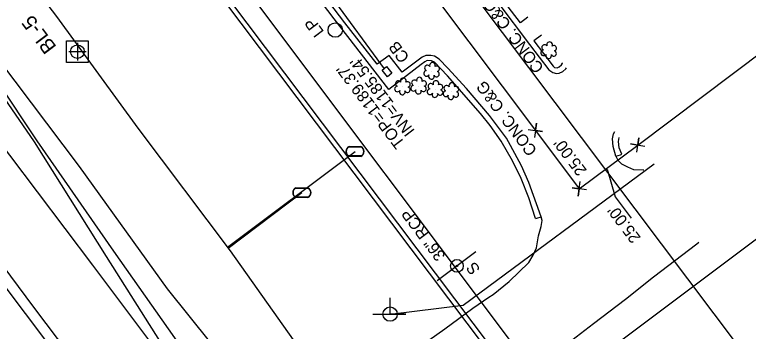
# Model space of a CAD drawing. Extents: x 1262092 to 1264624, y 774970 to 778314.
# Drawn here: x 1263792.5 to 1264043.6, y 776024.1 to 776132.5 of the extents above; entities that cross this region are included whole.
import ezdxf

# ---------------------------------------------------------------- set-up
doc = ezdxf.new("R2010")
doc.units = 0
for name, color, linetype in [('COGO Default Parcel', 7, 'Continuous'), ('Cogo Default Point CELL', 7, 'Continuous'), ('CTL Secondary Horizontal and Vertical CELL', 7, 'Continuous'), ('Exist Horizontal Alignment Station Label', 7, 'Continuous'), ('Exist Horizontal Alignment Tick Large', 7, 'Continuous'), ('Exist Property Corner CELL', 7, 'Continuous'), ('Exist Property Line', 7, 'Continuous'), ('Exist Property Line Leader', 7, 'Continuous'), ('Exist Property Line Text', 7, 'Continuous'), ('Exist Right of Way Easement Line', 7, 'Continuous'), ('Exist Right of Way Line', 7, 'Continuous'), ('Exist Roads Curbs', 7, 'Continuous'), ('Exist Roads EOP', 7, 'Continuous'), ('Exist Roads EOP Other', 7, 'Continuous'), ('Exist Roads EOT', 7, 'Continuous'), ('Exist Structure Minor Catch Basin Text', 7, 'Continuous'), ('Exist Structure Minor Drop Inlet', 7, 'Continuous'), ('Exist Structure Minor Drop Inlet Top Elevation', 7, 'Continuous'), ('Exist Structure Minor Pipes HDPE 15 Inch', 7, 'Continuous'), ('Exist Structure Minor Pipes HDPE 15 Inch Invert', 7, 'Continuous'), ('Exist Structure Minor Pipes RCP 36 Inch', 7, 'Continuous'), ('Exist Structure Minor Pipes RCP 36 Inch Text', 7, 'Continuous'), ('Exist Utilities Gas UG Line SUE LOS B', 7, 'Continuous'), ('Exist Utilities Other Pole Text', 7, 'Continuous'), ('Exist Utilities Power Joint Use Telephone CELL', 7, 'Continuous'), ('Exist Utilities Power UG Cable SUE LOS B', 7, 'Continuous'), ('Exist Utilities Water Meter CELL', 7, 'Continuous'), ('Exist Utilities Water UG Line SUE LOS B', 7, 'Continuous'), ('Prop Conc 4in Sidewalk', 7, 'Continuous'), ('Prop Paved Shoulder', 7, 'Continuous'), ('Sheet Plot Border Outside CELL', 7, 'Continuous')]:
    doc.layers.add(name, color=color, linetype=linetype)

# ---------------------------------------------------------------- blocks, each defined once
blk = doc.blocks.new('CTL SECONDARY HORIZONTAL AND VERTICAL')
at = {"layer": 'CTL Secondary Horizontal and Vertical CELL'}
blk.add_line((0, 0), (0, 0), dxfattribs=at)
blk.add_lwpolyline([(-0.1043, 0.0004), (0.0005, 0.1052), (0.1055, 0.0002), (0.0007, -0.1047)], close=True, dxfattribs=at)
blk = doc.blocks.new('EXIST UTILITIES WATER METER')
at = {"layer": 'Exist Utilities Water Meter CELL'}
blk.add_line((0, 0), (0, 0), dxfattribs=at)
for points in [[(-0.0408, 0.034), (0.0408, 0.034)], [(-0.0408, 0.0312), (0.0408, 0.0312)], [(0.0408, -0.0312), (-0.0413, -0.0312)], [(0.0408, -0.034), (-0.0413, -0.034)]]:
    blk.add_lwpolyline(points, dxfattribs=at)
for centre, radius, start, end in [((-0.0261, -0.0001), 0.0371, 113.178, 245.9794), ((-0.0259, -0.0001), 0.0347, 115.3009, 243.7824), ((0.0259, 0), 0.0371, 293.6483, 66.3084), ((0.0261, 0), 0.0345, 295.1272, 64.8728)]:
    blk.add_arc(centre, radius, start, end, dxfattribs=at)

msp = doc.modelspace()

# ---------------------------------------------------------------- linework, layer by layer
at = {"layer": 'COGO Default Parcel'}
msp.add_line((1263602.12, 776600.93), (1264624.2, 775243.33), dxfattribs=at)
at = {"layer": 'Cogo Default Point CELL'}
for points in [[(1263813.99, 776122.81), (1263813.99, 776119.81)], [(1263810.99, 776119.81), (1263813.99, 776119.81)], [(1263813.99, 776119.81), (1263816.99, 776119.81)], [(1263813.99, 776119.81), (1263813.99, 776116.81)]]:
    msp.add_lwpolyline(points, dxfattribs=at)
msp.add_circle((1263813.99, 776119.81), 2.34, dxfattribs=at)
at = {"layer": 'Exist Horizontal Alignment Station Label'}
msp.add_line((1263950.33, 776051.32), (1263937.11, 776041.42), dxfattribs=at)
for radius in [2.18, 0.24]:
    msp.add_circle((1263943.85, 776046.53), radius, dxfattribs=at)
at = {"layer": 'Exist Horizontal Alignment Tick Large'}
for p, q in [((1263975.34, 776120.1), (1263975.34, 776120.1)), ((1263935.25, 776113.07), (1263935.25, 776113.07)), ((1263925.29, 776107.72), (1263925.29, 776107.72)), ((1263930.8, 776108.01), (1263930.8, 776108.01)), ((1263936.44, 776106.81), (1263936.44, 776106.81)), ((1263941.87, 776106.12), (1263941.87, 776106.12))]:
    msp.add_line(p, q, dxfattribs=at)
for centre, radius, start, end in [((1263975.57, 776122.14), 0.99, 334.8391, 200.4717), ((1263973.54, 776119.39), 0.955, 95.1099, 327.9534), ((1263973.85, 776121.22), 0.968, 35.8908, 245.4216), ((1263977.01, 776120.97), 0.929, 284.4567, 126.0861), ((1263975.21, 776118.41), 0.984, 151.2797, 21.387), ((1263976.97, 776119.17), 0.937, 204.9913, 73.4601), ((1263933.77, 776114.2), 0.968, 35.8908, 245.4216), ((1263935.48, 776115.11), 0.99, 334.8391, 200.4717), ((1263933.45, 776112.37), 0.955, 95.1099, 327.9534), ((1263936.89, 776112.14), 0.937, 204.9913, 73.4601), ((1263936.93, 776113.94), 0.929, 284.4567, 126.0861), ((1263925.52, 776109.76), 0.99, 334.8391, 200.4717), ((1263931.03, 776110.05), 0.99, 334.8391, 200.4717), ((1263935.12, 776111.39), 0.984, 151.2797, 21.387), ((1263923.49, 776107.02), 0.955, 95.1099, 327.9534), ((1263923.8, 776108.85), 0.968, 35.8908, 245.4216), ((1263926.92, 776106.79), 0.937, 204.9913, 73.4601), ((1263926.96, 776108.59), 0.929, 284.4567, 126.0861), ((1263929, 776107.3), 0.955, 95.1099, 327.9534), ((1263929.32, 776109.13), 0.968, 35.8908, 245.4216), ((1263932.44, 776107.08), 0.937, 204.9913, 73.4601), ((1263932.47, 776108.88), 0.929, 284.4567, 126.0861), ((1263934.95, 776107.94), 0.968, 35.8908, 245.4216), ((1263936.66, 776108.85), 0.99, 334.8391, 200.4717), ((1263938.11, 776107.68), 0.929, 284.4567, 126.0861), ((1263940.39, 776107.25), 0.968, 35.8908, 245.4216), ((1263942.1, 776108.16), 0.99, 334.8391, 200.4717), ((1263943.54, 776106.99), 0.929, 284.4567, 126.0861), ((1263925.16, 776106.04), 0.984, 151.2797, 21.387), ((1263930.67, 776106.32), 0.984, 151.2797, 21.387), ((1263934.63, 776106.1), 0.955, 95.1099, 327.9534), ((1263936.31, 776105.13), 0.984, 151.2797, 21.387), ((1263938.07, 776105.88), 0.937, 204.9913, 73.4601), ((1263940.07, 776105.42), 0.955, 95.1099, 327.9534), ((1263943.51, 776105.19), 0.937, 204.9913, 73.4601), ((1263941.74, 776104.44), 0.984, 151.2797, 21.387)]:
    msp.add_arc(centre, radius, start, end, dxfattribs=at)
at = {"layer": 'Exist Property Corner CELL'}
for p, q in [((1263970.72, 776092.86), (1263970.72, 776092.86)), ((1264005.72, 776087.87), (1264005.72, 776087.87)), ((1263985.72, 776072.87), (1263985.72, 776072.87))]:
    msp.add_line(p, q, dxfattribs=at)
for points in [[(1263968.24, 776093.21), (1263973.19, 776092.51), (1263970.72, 776092.86), (1263971.07, 776095.34), (1263970.36, 776090.39)], [(1264005.37, 776085.4), (1264006.07, 776090.35), (1264005.72, 776087.87), (1264003.24, 776088.22), (1264008.19, 776087.52)], [(1263988.2, 776072.51), (1263983.25, 776073.22), (1263985.72, 776072.87), (1263985.37, 776070.39), (1263986.08, 776075.34)]]:
    msp.add_lwpolyline(points, dxfattribs=at)
at = {"layer": 'Exist Property Line'}
for p, q in [((1263879.77, 776214.05), (1263970.72, 776092.86)), ((1264005.72, 776087.87), (1264124.93, 776177.33)), ((1263970.72, 776092.86), (1263985.72, 776072.87)), ((1263985.72, 776072.87), (1264005.72, 776087.87))]:
    msp.add_line(p, q, dxfattribs=at)
at = {"layer": 'Exist Property Line Leader'}
msp.add_lwpolyline([(1263995.3, 776079.59), (1263997.97, 776070.12), (1264003.43, 776062.87)], dxfattribs=at)
at = {"layer": 'Exist Right of Way Easement Line'}
for q in [(1263824.78, 776204.04), (1264214.93, 776182.35)]:
    msp.add_line((1263975.74, 776002.86), q, dxfattribs=at)
at = {"layer": 'Exist Right of Way Line'}
msp.add_line((1263590.4, 776500.74), (1264585.76, 775179.25), dxfattribs=at)
at = {"layer": 'Exist Roads Curbs'}
for points in [[(1263970.77, 776062.71), (1263968.43, 776069.85), (1263965.8, 776076.37), (1263962.89, 776082.43), (1263959.02, 776089.14), (1263955.18, 776094.49), (1263951.97, 776098.62), (1263940.6, 776111.57), (1263936.2, 776116.19), (1263935.12, 776116.72), (1263933.7, 776116.74), (1263932.93, 776116.36), (1263931.67, 776115.39), (1263920.52, 776106.91), (1263901.9, 776131.06), (1263887.03, 776150.59)], [(1263968.15, 776131.58), (1263965.61, 776129.67), (1263959.42, 776137.8), (1263958.9, 776138.82), (1263958.97, 776139.75), (1263959.22, 776140.19), (1263960.03, 776140.82), (1263960.86, 776141.17)], [(1263972.81, 776125.46), (1263970.23, 776123.48), (1263976.8, 776114.79), (1263977.27, 776114.38), (1263978.19, 776114.26), (1263978.79, 776114.57), (1263979.62, 776115.3), (1263979.98, 776115.83), (1263979.99, 776116)], [(1264000.31, 776084.74), (1263999.38, 776086.87), (1263999.12, 776089.03), (1263999.39, 776090.49)]]:
    msp.add_lwpolyline(points, dxfattribs=at)
at = {"layer": 'Exist Roads EOP'}
for points in [[(1263635.67, 776235.21), (1263664.15, 776199.52), (1263694.11, 776162.22), (1263723.19, 776125.55), (1263739.53, 776104.93), (1263766.81, 776069.09), (1263796.15, 776030.19), (1263824.31, 775992.83), (1263865.34, 775938.5), (1263893.23, 775901.06), (1263922.52, 775862.2), (1263949.95, 775825.28), (1263977.99, 775788.17), (1264005.13, 775752.44), (1264032.99, 775715.55), (1264060.75, 775678.62), (1264088.38, 775641.53), (1264133.95, 775582.22)], [(1263749.6, 776164.9), (1263758.59, 776150.74), (1263772.63, 776130.47), (1263800.11, 776089.27), (1263826.34, 776051.57), (1263853.69, 776012.65)]]:
    msp.add_lwpolyline(points, dxfattribs=at)
at = {"layer": 'Exist Roads EOP Other'}
for points in [[(1263970.77, 776062.71), (1263971.24, 776062.87), (1263972.7, 776063.35), (1263968.46, 776075.08), (1263965.97, 776080.79), (1263962.16, 776087.72), (1263960.79, 776090.25), (1263955, 776097.98), (1263947.19, 776107.17), (1263940.79, 776114.12), (1263937.76, 776117.29), (1263936.16, 776118.22), (1263934.94, 776118.54), (1263933.26, 776118.53), (1263931.97, 776117.93), (1263925.07, 776112.82), (1263920.62, 776118.54), (1263916.52, 776115.49), (1263905.47, 776129.71), (1263894.55, 776144.1)], [(1263959.54, 776142.9), (1263959.14, 776142.75), (1263957.98, 776141.76), (1263957.23, 776140.48), (1263956.94, 776139.21), (1263957.15, 776138), (1263957.85, 776136.64), (1263968.68, 776122.22), (1263975.31, 776113.59), (1263976.67, 776112.68), (1263977.98, 776112.34), (1263978.86, 776112.5), (1263980.11, 776113.04), (1263981.08, 776113.93), (1263981.31, 776114.26)], [(1263998.23, 776084.06), (1263997.3, 776087.32), (1263997.1, 776090.01), (1263997.47, 776091.73), (1263997.84, 776092.53)], [(1263998.23, 776084.06), (1263999.85, 776084.54), (1264000.31, 776084.74)], [(1263998.23, 776084.06), (1263998.96, 776082.63), (1264000.17, 776081.45), (1264002.23, 776080.41), (1264004.3, 776079.55), (1264007.61, 776079.38), (1264007.82, 776079.41)], [(1263929.54, 776017.8), (1263939.71, 776024.94), (1263949.33, 776032.09), (1263954.8, 776035.88), (1263956.3, 776036.71), (1263961.74, 776041.19), (1263968.51, 776047.63), (1263969.96, 776050.21), (1263971.05, 776052.75), (1263971.82, 776056.8), (1263972.66, 776060.04), (1263973.01, 776062.08), (1263972.7, 776063.35)], [(1263947.26, 775994.36), (1263953.48, 776000.71), (1263953.48, 776000.71), (1263960.57, 776005.38), (1263965.59, 776008.58), (1263974.55, 776014.6), (1263983.22, 776021.07), (1263990.61, 776026.78), (1264001.49, 776035.16), (1264011.13, 776042.77), (1264025.97, 776054.06), (1264026.67, 776054.61)]]:
    msp.add_lwpolyline(points, dxfattribs=at)
at = {"layer": 'Exist Roads EOT'}
for points in [[(1263634.71, 776293.29), (1263661.92, 776255.81), (1263688.91, 776219.66), (1263718.75, 776179.84), (1263747.13, 776142.27), (1263762.04, 776122.53), (1263790.78, 776084.44), (1263819.18, 776046.81), (1263847.86, 776008.49), (1263857.04, 775996.7)], [(1263607.01, 776274.46), (1263637.64, 776236.73), (1263666.33, 776201.02), (1263696.03, 776164.2), (1263725.98, 776127.31), (1263742.41, 776107.39), (1263769.94, 776071.32), (1263798.94, 776032.46), (1263827.52, 775994.61), (1263868.02, 775940.4), (1263896.06, 775903.09), (1263925.16, 775864.32), (1263952.94, 775827.49), (1263980.85, 775790.42), (1264008.12, 775754.34), (1264035.58, 775717.72), (1264063.46, 775680.83), (1264091.3, 775643.74), (1264117.07, 775609.33), (1264137.68, 775581.96)], [(1263742.49, 776168.2), (1263771.27, 776129.47), (1263799.2, 776088.97), (1263823.8, 776049.73), (1263849.17, 776009.73), (1263887.89, 775955), (1263915.93, 775917.26), (1263944.39, 775879.47), (1263973.23, 775841.39), (1264000.39, 775805.7), (1264028.66, 775767.4), (1264055.46, 775731.81), (1264085.03, 775692.75)]]:
    msp.add_lwpolyline(points, dxfattribs=at)
at = {"layer": 'Exist Structure Minor Drop Inlet'}
msp.add_lwpolyline([(1263919.73, 776114.68), (1263921.58, 776112.43), (1263920.07, 776111.24), (1263918.3, 776113.52), (1263919.73, 776114.68)], dxfattribs=at)
at = {"layer": 'Exist Structure Minor Pipes HDPE 15 Inch'}
msp.add_line((1263854.08, 776202.53), (1263918.97, 776113.98), dxfattribs=at)
at = {"layer": 'Exist Structure Minor Pipes RCP 36 Inch'}
msp.add_line((1263762.85, 776274.58), (1263973.73, 775994.48), dxfattribs=at)
at = {"layer": 'Exist Utilities Gas UG Line SUE LOS B'}
msp.add_lwpolyline([(1263999.19, 775839.39), (1263985.7, 775869), (1263961.35, 775898.49), (1263933.55, 775929.39), (1263903.92, 775964.01), (1263874.9, 776001.17), (1263844.84, 776038.67), (1263814.72, 776080.57), (1263786.93, 776117.1), (1263768.77, 776141.15), (1263740.07, 776178.28), (1263709.03, 776220.12), (1263678.63, 776261.22), (1263654.09, 776299.54), (1263639.97, 776350.31), (1263613.73, 776383.62), (1263581.55, 776427.09), (1263558.06, 776458.02), (1263528.1, 776503.73), (1263523.32, 776512.13)], dxfattribs=at)
msp.add_circle((1263902.21, 776127.19), 2.46, dxfattribs=at)
at = {"layer": 'Exist Utilities Power Joint Use Telephone CELL'}
msp.add_line((1263920.98, 776030.01), (1263920.98, 776030.01), dxfattribs=at)
msp.add_lwpolyline([(1263915.05, 776030.01), (1263926.38, 776029.97), (1263920.98, 776029.99), (1263920.98, 776035.64)], dxfattribs=at)
msp.add_circle((1263920.98, 776030.02), 2.45, dxfattribs=at)
at = {"layer": 'Exist Utilities Power UG Cable SUE LOS B'}
msp.add_lwpolyline([(1263920.98, 776029.99), (1263946.04, 776033.11), (1264011.36, 776081.45)], dxfattribs=at)
at = {"layer": 'Exist Utilities Water UG Line SUE LOS B'}
for p, q in [((1263865.38, 776052.93), (1263908.98, 776085.68)), ((1263865.61, 776052.64), (1263890.81, 776071.57))]:
    msp.add_line(p, q, dxfattribs=at)
msp.add_lwpolyline([(1263947.84, 775937.63), (1263921.48, 775975.65), (1263891.78, 776015.72), (1263866.35, 776051.64), (1263834.78, 776093.68), (1263806.91, 776131.82), (1263785.84, 776159.4), (1263762.42, 776192.1), (1263728.85, 776233.86), (1263701.99, 776270.27), (1263670.29, 776315.62), (1263645.61, 776350.98), (1263620.38, 776389.35), (1263590.58, 776434.56), (1263568.12, 776469.9), (1263541.87, 776510.41), (1263521.01, 776540.13)], dxfattribs=at)

# ---------------------------------------------------------------- block references
at = {"layer": 'CTL Secondary Horizontal and Vertical CELL', "xscale": 50, "yscale": 49.99999999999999, "rotation": 44.99999999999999}
msp.add_blockref('CTL SECONDARY HORIZONTAL AND VERTICAL', (1263813.99, 776119.81), dxfattribs=at)
msp.add_blockref('CTL SECONDARY HORIZONTAL AND VERTICAL', (1263813.99, 776119.81), dxfattribs=at)
at = {"layer": 'Exist Utilities Water Meter CELL', "xscale": 50, "yscale": 50}
for p in [(1263908.98, 776085.68), (1263890.81, 776071.57)]:
    msp.add_blockref('EXIST UTILITIES WATER METER', p, dxfattribs=at)

# ---------------------------------------------------------------- texts
at = {"layer": 'Exist Property Line Text'}
for rotation, p in [(126.885, (1263988.49, 776079.21)), (126.9746, (1264006.95, 776056.21))]:
    msp.add_text("25.00'", height=4, rotation=rotation, dxfattribs=at).set_placement(p)
at = {"layer": 'Exist Structure Minor Catch Basin Text'}
msp.add_text('CB', height=4, rotation=126.9874, dxfattribs=at).set_placement((1263927.79, 776117.86))
at = {"layer": 'Exist Structure Minor Drop Inlet Top Elevation'}
msp.add_text("TOP=1189.37'", height=4, rotation=126.9874, dxfattribs=at).set_placement((1263926.24, 776088.51))
at = {"layer": 'Exist Structure Minor Pipes HDPE 15 Inch Invert'}
msp.add_text("INV=1185.54'", height=4, rotation=126.9874, dxfattribs=at).set_placement((1263929.62, 776092.72))
at = {"layer": 'Exist Structure Minor Pipes RCP 36 Inch Text'}
msp.add_text('36" RCP', height=4, rotation=126.9757, dxfattribs=at).set_placement((1263940.16, 776050.09))
at = {"layer": 'Exist Utilities Other Pole Text'}
msp.add_text('LP', height=4, rotation=126.9746, dxfattribs=at).set_placement((1263898.54, 776126.64))
at = {"layer": 'Prop Conc 4in Sidewalk'}
msp.add_text('BL-5', height=5, rotation=126.9874, dxfattribs=at).set_placement((1263807.02, 776121.46))
at = {"layer": 'Prop Paved Shoulder'}
msp.add_text('S', height=4, rotation=126.9874, dxfattribs=at).set_placement((1263952.03, 776045.38))
at = {"layer": 'Sheet Plot Border Outside CELL'}
for p in [(1263973.8, 776114.3), (1263971.48, 776086)]:
    msp.add_text('CONC. C&G', height=4, rotation=126.8505, dxfattribs=at).set_placement(p)

doc.saveas('drawing.dxf')
